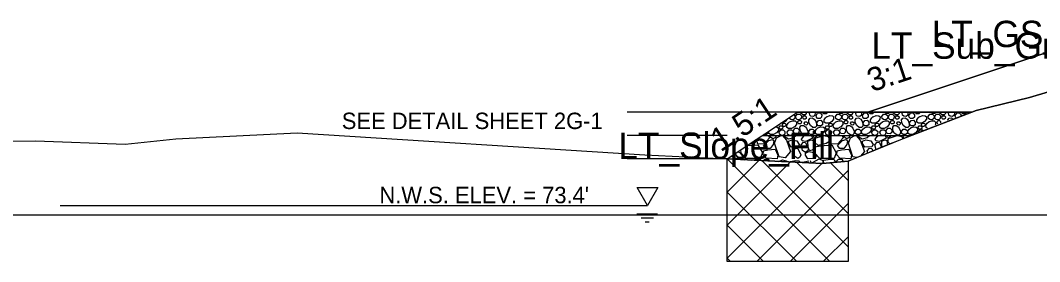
# Model space of a CAD drawing. Extents: x -14026 to 1303, y -10 to 9533.
# Drawn here: x 85.51 to 129.01, y 3498 to 3508.3 of the extents above; entities that cross this region are included whole.
import ezdxf

# ---------------------------------------------------------------- set-up
doc = ezdxf.new("R2010")
doc.units = 0
for name, color, linetype in [('Exist Cross Section Cell', 7, 'Continuous'), ('Exist XS Ground Line', 7, 'Continuous'), ('Old_Level_10', 7, 'Continuous'), ('Prop CMT Slope Grass', 7, 'Continuous'), ('Prop CMT Subgrade Earthwork', 7, 'Continuous'), ('Prop XS Earthwork Shape', 7, 'Continuous'), ('Prop XS Side Slope Text', 7, 'Continuous'), ('Scratch_Level_0', 7, 'Continuous'), ('Scratch_Level_1', 7, 'Continuous'), ('Scratch_Level_3', 7, 'Continuous'), ('Scratch_Level_5', 7, 'Continuous')]:
    doc.layers.add(name, color=color, linetype=linetype)

msp = doc.modelspace()

# ---------------------------------------------------------------- linework, layer by layer
at = {"layer": 'Exist Cross Section Cell'}
msp.add_line((0, 3500), (150, 3500), dxfattribs=at)
at = {"layer": 'Exist XS Ground Line'}
msp.add_lwpolyline([(80.656, 3503.087), (86.162, 3503.158), (89.984, 3503.012), (92.146, 3503.237), (97.323, 3503.503), (112.156, 3502.557), (119.746, 3502.185), (120.837, 3502.289), (122.384, 3502.944), (126.299, 3504.454), (128.568, 3505.004), (131.672, 3505.924)], dxfattribs=at)
at = {"layer": 'Old_Level_10'}
for p, q in [((119.183, 3504.338), (119.215, 3504.384)), ((121.162, 3504.338), (121.194, 3504.384)), ((122.702, 3504.384), (126.118, 3504.384)), ((123.14, 3504.338), (123.173, 3504.384)), ((125.119, 3504.338), (125.151, 3504.384)), ((117.177, 3503.384), (123.525, 3503.384)), ((123.208, 3503.255), (123.172, 3503.384)), ((123.828, 3503.519), (123.827, 3503.524)), ((116.897, 3503.197), (116.921, 3503.141)), ((117.463, 3502.306), (117.463, 3502.297)), ((119.209, 3502.318), (119.265, 3502.208)), ((120.284, 3502.262), (120.247, 3502.232)), ((120.611, 3502.306), (120.61, 3502.267))]:
    msp.add_line(p, q, dxfattribs=at)
msp.add_lwpolyline([(115.677, 3502.384), (118.677, 3504.384), (126.118, 3504.384), (123.525, 3503.384), (120.837, 3502.289), (119.746, 3502.185)], close=True, dxfattribs=at)
for points in [[(118.514, 3504.276), (118.568, 3504.22), (118.557, 3504.112), (118.491, 3504.057), (118.385, 3504.065), (118.335, 3504.113), (118.327, 3504.151)], [(118.624, 3504.349), (118.6, 3504.323), (118.586, 3504.323)], [(118.595, 3504.192), (118.662, 3504.288), (118.77, 3504.294), (118.844, 3504.216), (118.833, 3504.108), (118.767, 3504.053), (118.661, 3504.06), (118.611, 3504.109), (118.595, 3504.192)], [(119.056, 3504.384), (119.05, 3504.317), (118.998, 3504.262), (118.904, 3504.264), (118.798, 3504.347), (118.779, 3504.384)], [(119.411, 3504.384), (119.432, 3504.363), (119.421, 3504.254), (119.355, 3504.199), (119.249, 3504.207), (119.199, 3504.255), (119.183, 3504.338)], [(119.467, 3504.243), (119.534, 3504.339), (119.641, 3504.345), (119.716, 3504.268), (119.705, 3504.159), (119.639, 3504.104), (119.533, 3504.112), (119.483, 3504.16), (119.467, 3504.243)], [(119.949, 3504.384), (119.947, 3504.362), (119.895, 3504.307), (119.801, 3504.308), (119.704, 3504.384)], [(120.219, 3504.384), (120.2, 3504.369), (120.094, 3504.376), (120.086, 3504.384)], [(120.297, 3504.196), (120.364, 3504.292), (120.472, 3504.298), (120.546, 3504.22), (120.536, 3504.112), (120.469, 3504.057), (120.363, 3504.065), (120.313, 3504.113), (120.297, 3504.196)], [(120.631, 3504.384), (120.631, 3504.378), (120.578, 3504.323), (120.485, 3504.325), (120.408, 3504.384)], [(120.574, 3504.192), (120.641, 3504.288), (120.748, 3504.294), (120.823, 3504.216), (120.812, 3504.108), (120.746, 3504.053), (120.64, 3504.06), (120.59, 3504.109), (120.574, 3504.192)], [(121.035, 3504.384), (121.029, 3504.317), (120.977, 3504.262), (120.883, 3504.264), (120.777, 3504.347), (120.758, 3504.384)], [(121.39, 3504.384), (121.411, 3504.363), (121.4, 3504.254), (121.334, 3504.199), (121.228, 3504.207), (121.178, 3504.255), (121.162, 3504.338)], [(121.446, 3504.243), (121.513, 3504.339), (121.62, 3504.345), (121.695, 3504.268), (121.684, 3504.159), (121.618, 3504.104), (121.512, 3504.112), (121.462, 3504.16), (121.446, 3504.243)], [(121.928, 3504.384), (121.926, 3504.362), (121.874, 3504.307), (121.78, 3504.308), (121.683, 3504.384)], [(122.198, 3504.384), (122.179, 3504.369), (122.073, 3504.376), (122.065, 3504.384)], [(122.276, 3504.196), (122.343, 3504.292), (122.45, 3504.298), (122.525, 3504.22), (122.514, 3504.112), (122.448, 3504.057), (122.342, 3504.065), (122.292, 3504.113), (122.276, 3504.196)], [(122.61, 3504.384), (122.609, 3504.378), (122.557, 3504.323), (122.463, 3504.325), (122.387, 3504.384)], [(122.552, 3504.192), (122.62, 3504.288), (122.727, 3504.294), (122.802, 3504.216), (122.791, 3504.108), (122.725, 3504.053), (122.619, 3504.06), (122.569, 3504.109), (122.553, 3504.192)], [(123.014, 3504.384), (123.008, 3504.317), (122.956, 3504.262), (122.862, 3504.264), (122.755, 3504.347), (122.737, 3504.384)], [(123.369, 3504.384), (123.389, 3504.363), (123.379, 3504.254), (123.312, 3504.199), (123.206, 3504.207), (123.157, 3504.255), (123.14, 3504.338)], [(123.424, 3504.243), (123.492, 3504.339), (123.599, 3504.345), (123.674, 3504.268), (123.663, 3504.159), (123.596, 3504.104), (123.49, 3504.112), (123.441, 3504.16), (123.424, 3504.243)], [(123.907, 3504.384), (123.905, 3504.362), (123.853, 3504.307), (123.759, 3504.308), (123.662, 3504.384)], [(124.177, 3504.384), (124.158, 3504.369), (124.052, 3504.376), (124.043, 3504.384)], [(124.255, 3504.196), (124.322, 3504.292), (124.429, 3504.298), (124.504, 3504.22), (124.493, 3504.112), (124.427, 3504.057), (124.321, 3504.065), (124.271, 3504.113), (124.255, 3504.196)], [(124.589, 3504.384), (124.588, 3504.378), (124.536, 3504.323), (124.442, 3504.325), (124.366, 3504.384)], [(124.531, 3504.192), (124.598, 3504.288), (124.706, 3504.294), (124.78, 3504.216), (124.77, 3504.108), (124.703, 3504.053), (124.597, 3504.06), (124.547, 3504.109), (124.531, 3504.192)], [(124.992, 3504.384), (124.987, 3504.317), (124.934, 3504.262), (124.841, 3504.264), (124.734, 3504.347), (124.715, 3504.384)], [(125.347, 3504.384), (125.368, 3504.363), (125.357, 3504.254), (125.291, 3504.199), (125.185, 3504.207), (125.135, 3504.255), (125.119, 3504.338)], [(125.403, 3504.243), (125.47, 3504.339), (125.578, 3504.345), (125.652, 3504.268), (125.648, 3504.221)], [(125.433, 3504.147), (125.419, 3504.16), (125.403, 3504.243)], [(125.885, 3504.384), (125.883, 3504.362), (125.831, 3504.307), (125.737, 3504.308), (125.64, 3504.384)], [(126.084, 3504.372), (126.03, 3504.376), (126.022, 3504.384)], [(118.238, 3504.092), (118.238, 3504.081), (118.155, 3503.975), (118.026, 3503.91), (117.965, 3503.909)], [(118.034, 3503.85), (118.074, 3503.908), (118.139, 3503.911), (118.184, 3503.865), (118.177, 3503.8), (118.137, 3503.767), (118.074, 3503.771), (118.044, 3503.8), (118.034, 3503.85)], [(118.334, 3503.963), (118.459, 3504.012), (118.575, 3504.003), (118.63, 3503.95), (118.628, 3503.857), (118.545, 3503.75), (118.416, 3503.686), (118.295, 3503.684), (118.226, 3503.732), (118.22, 3503.829), (118.275, 3503.915), (118.339, 3503.966)], [(118.693, 3503.961), (118.733, 3504.018), (118.798, 3504.022), (118.842, 3503.975), (118.836, 3503.91), (118.796, 3503.877), (118.733, 3503.882), (118.703, 3503.911), (118.693, 3503.961)], [(119.059, 3503.7), (119.109, 3503.574), (119.099, 3503.459), (119.047, 3503.404), (118.953, 3503.406), (118.847, 3503.489), (118.782, 3503.618), (118.78, 3503.739), (118.829, 3503.807), (118.925, 3503.814), (119.012, 3503.758), (119.063, 3503.695)], [(118.901, 3504.162), (118.941, 3504.22), (119.006, 3504.223), (119.05, 3504.177), (119.044, 3504.112), (119.004, 3504.079), (118.941, 3504.084), (118.911, 3504.113), (118.901, 3504.162)], [(118.958, 3503.913), (118.998, 3503.971), (119.062, 3503.974), (119.107, 3503.928), (119.101, 3503.863), (119.061, 3503.83), (118.997, 3503.834), (118.967, 3503.864), (118.958, 3503.913)], [(119.44, 3504.017), (119.49, 3503.892), (119.48, 3503.776), (119.427, 3503.721), (119.334, 3503.723), (119.227, 3503.806), (119.163, 3503.935), (119.161, 3504.056), (119.209, 3504.125), (119.306, 3504.131), (119.392, 3504.076), (119.443, 3504.012)], [(119.497, 3503.929), (119.564, 3504.024), (119.671, 3504.031), (119.746, 3503.953), (119.735, 3503.845), (119.669, 3503.79), (119.563, 3503.797), (119.513, 3503.846), (119.497, 3503.929)], [(119.922, 3504.187), (120.048, 3504.237), (120.164, 3504.227), (120.218, 3504.175), (120.217, 3504.081), (120.133, 3503.975), (120.005, 3503.91), (119.883, 3503.908), (119.815, 3503.957), (119.808, 3504.053), (119.864, 3504.14), (119.927, 3504.191)], [(120.013, 3503.85), (120.053, 3503.908), (120.117, 3503.911), (120.162, 3503.865), (120.156, 3503.8), (120.116, 3503.767), (120.052, 3503.771), (120.022, 3503.8), (120.013, 3503.85)], [(120.312, 3503.963), (120.438, 3504.012), (120.554, 3504.003), (120.609, 3503.95), (120.607, 3503.857), (120.524, 3503.75), (120.395, 3503.686), (120.273, 3503.684), (120.205, 3503.732), (120.199, 3503.829), (120.254, 3503.915), (120.317, 3503.966)], [(120.672, 3503.961), (120.712, 3504.018), (120.776, 3504.022), (120.821, 3503.975), (120.815, 3503.91), (120.775, 3503.877), (120.711, 3503.882), (120.681, 3503.911), (120.672, 3503.961)], [(121.038, 3503.7), (121.088, 3503.574), (121.078, 3503.459), (121.026, 3503.404), (120.932, 3503.406), (120.825, 3503.489), (120.761, 3503.618), (120.759, 3503.739), (120.807, 3503.807), (120.904, 3503.814), (120.991, 3503.758), (121.041, 3503.695)], [(120.88, 3504.162), (120.92, 3504.22), (120.984, 3504.223), (121.029, 3504.177), (121.023, 3504.112), (120.983, 3504.079), (120.919, 3504.084), (120.889, 3504.113), (120.88, 3504.162)], [(120.936, 3503.913), (120.977, 3503.971), (121.041, 3503.974), (121.086, 3503.928), (121.079, 3503.863), (121.04, 3503.83), (120.976, 3503.834), (120.946, 3503.864), (120.936, 3503.913)], [(121.418, 3504.017), (121.468, 3503.892), (121.458, 3503.776), (121.406, 3503.721), (121.312, 3503.723), (121.206, 3503.806), (121.141, 3503.935), (121.139, 3504.056), (121.188, 3504.125), (121.285, 3504.131), (121.371, 3504.076), (121.422, 3504.012)], [(121.476, 3503.929), (121.543, 3504.024), (121.65, 3504.031), (121.725, 3503.953), (121.714, 3503.845), (121.648, 3503.79), (121.542, 3503.797), (121.492, 3503.846), (121.476, 3503.929)], [(121.901, 3504.187), (122.027, 3504.237), (122.142, 3504.227), (122.197, 3504.175), (122.195, 3504.081), (122.112, 3503.975), (121.983, 3503.91), (121.862, 3503.908), (121.794, 3503.957), (121.787, 3504.053), (121.843, 3504.14), (121.906, 3504.191)], [(121.991, 3503.85), (122.032, 3503.908), (122.096, 3503.911), (122.141, 3503.865), (122.134, 3503.8), (122.095, 3503.767), (122.031, 3503.771), (122.001, 3503.8), (121.991, 3503.85)], [(122.291, 3503.963), (122.417, 3504.012), (122.532, 3504.003), (122.587, 3503.95), (122.586, 3503.857), (122.502, 3503.75), (122.373, 3503.686), (122.252, 3503.684), (122.184, 3503.732), (122.177, 3503.829), (122.233, 3503.915), (122.296, 3503.966)], [(122.65, 3503.961), (122.691, 3504.018), (122.755, 3504.022), (122.8, 3503.975), (122.793, 3503.91), (122.754, 3503.877), (122.69, 3503.882), (122.66, 3503.911), (122.65, 3503.961)], [(123.017, 3503.7), (123.067, 3503.574), (123.057, 3503.459), (123.004, 3503.404), (122.911, 3503.406), (122.804, 3503.489), (122.74, 3503.618), (122.738, 3503.739), (122.786, 3503.807), (122.883, 3503.814), (122.969, 3503.758), (123.02, 3503.695)], [(122.858, 3504.162), (122.899, 3504.22), (122.963, 3504.223), (123.008, 3504.177), (123.001, 3504.112), (122.962, 3504.079), (122.898, 3504.084), (122.868, 3504.113), (122.858, 3504.162)], [(122.915, 3503.913), (122.955, 3503.971), (123.02, 3503.974), (123.065, 3503.928), (123.058, 3503.863), (123.018, 3503.83), (122.955, 3503.834), (122.925, 3503.864), (122.915, 3503.913)], [(123.397, 3504.017), (123.447, 3503.892), (123.437, 3503.776), (123.385, 3503.721), (123.291, 3503.723), (123.185, 3503.806), (123.12, 3503.935), (123.118, 3504.056), (123.167, 3504.125), (123.263, 3504.131), (123.35, 3504.076), (123.4, 3504.012)], [(123.454, 3503.929), (123.521, 3504.024), (123.629, 3504.031), (123.703, 3503.953), (123.693, 3503.845), (123.626, 3503.79), (123.52, 3503.797), (123.47, 3503.846), (123.454, 3503.929)], [(123.88, 3504.187), (124.005, 3504.237), (124.121, 3504.227), (124.176, 3504.175), (124.174, 3504.081), (124.091, 3503.975), (123.962, 3503.91), (123.841, 3503.908), (123.772, 3503.957), (123.766, 3504.053), (123.821, 3504.14), (123.885, 3504.191)], [(123.97, 3503.85), (124.01, 3503.908), (124.075, 3503.911), (124.12, 3503.865), (124.113, 3503.8), (124.073, 3503.767), (124.01, 3503.771), (123.98, 3503.8), (123.97, 3503.85)], [(124.218, 3503.693), (124.162, 3503.732), (124.156, 3503.829), (124.211, 3503.915), (124.275, 3503.966)], [(124.27, 3503.963), (124.396, 3504.012), (124.511, 3504.003), (124.566, 3503.95), (124.564, 3503.857), (124.553, 3503.842)], [(124.629, 3503.961), (124.669, 3504.018), (124.734, 3504.022), (124.779, 3503.975), (124.773, 3503.919)], [(124.668, 3503.882), (124.639, 3503.911), (124.629, 3503.961)], [(124.837, 3504.162), (124.877, 3504.22), (124.942, 3504.223), (124.987, 3504.177), (124.98, 3504.112), (124.94, 3504.079), (124.877, 3504.084), (124.847, 3504.113), (124.837, 3504.162)], [(125.097, 3504.031), (125.097, 3504.056), (125.145, 3504.125), (125.242, 3504.131), (125.293, 3504.099)], [(117.434, 3503.384), (117.473, 3503.278), (117.246, 3503.024), (116.984, 3503.007), (116.924, 3503.216)], [(117.423, 3503.548), (117.416, 3503.475), (117.35, 3503.42), (117.244, 3503.428), (117.243, 3503.428)], [(117.73, 3503.753), (117.806, 3503.746), (117.861, 3503.694), (117.86, 3503.6), (117.776, 3503.494), (117.647, 3503.429), (117.526, 3503.427), (117.458, 3503.476), (117.452, 3503.567)], [(117.624, 3503.24), (117.527, 3503.317), (117.502, 3503.384)], [(117.758, 3503.384), (117.734, 3503.301), (117.624, 3503.24)], [(118.035, 3503.378), (118.199, 3503.184), (118.381, 3502.704), (118.155, 3502.426), (117.89, 3502.471), (117.698, 3503.058), (117.782, 3503.286), (117.973, 3503.384)], [(117.891, 3503.524), (117.958, 3503.619), (118.065, 3503.625), (118.14, 3503.548), (118.129, 3503.44), (118.063, 3503.384), (117.957, 3503.392), (117.907, 3503.44), (117.891, 3503.524)], [(117.895, 3503.734), (117.936, 3503.791), (118, 3503.795), (118.045, 3503.748), (118.038, 3503.683), (117.999, 3503.65), (117.935, 3503.655), (117.905, 3503.684), (117.895, 3503.734)], [(118.617, 3503.384), (118.506, 3503.281), (118.289, 3503.228), (118.148, 3503.31), (118.142, 3503.384)], [(118.238, 3503.527), (118.305, 3503.623), (118.412, 3503.629), (118.487, 3503.552), (118.476, 3503.443), (118.41, 3503.388), (118.304, 3503.396), (118.254, 3503.444), (118.238, 3503.527)], [(118.498, 3503.598), (118.566, 3503.693), (118.673, 3503.699), (118.748, 3503.622), (118.737, 3503.514), (118.67, 3503.458), (118.564, 3503.466), (118.515, 3503.514), (118.498, 3503.598)], [(118.839, 3503.232), (118.94, 3503.354), (118.979, 3503.384)], [(119.273, 3503.384), (119.313, 3503.263), (119.026, 3503.121), (118.875, 3503.151), (118.839, 3503.232)], [(119.156, 3503.559), (119.223, 3503.655), (119.331, 3503.661), (119.405, 3503.583), (119.395, 3503.475), (119.328, 3503.42), (119.222, 3503.428), (119.172, 3503.476), (119.156, 3503.559)], [(119.38, 3503.28), (119.338, 3503.372), (119.332, 3503.384)], [(119.543, 3503.384), (119.49, 3503.34), (119.38, 3503.28)], [(120.069, 3503.141), (119.904, 3503.041), (119.551, 3502.958), (119.395, 3503.101), (119.389, 3503.251), (119.784, 3503.384)], [(119.544, 3503.706), (119.67, 3503.756), (119.785, 3503.746), (119.84, 3503.694), (119.838, 3503.6), (119.755, 3503.494), (119.626, 3503.429), (119.505, 3503.427), (119.436, 3503.476), (119.43, 3503.573), (119.485, 3503.659), (119.549, 3503.71)], [(119.799, 3503.384), (119.98, 3503.344), (120.069, 3503.141)], [(119.87, 3503.524), (119.937, 3503.619), (120.044, 3503.625), (120.119, 3503.548), (120.108, 3503.44), (120.042, 3503.384), (119.936, 3503.392), (119.886, 3503.44), (119.87, 3503.524)], [(119.874, 3503.734), (119.914, 3503.791), (119.979, 3503.795), (120.024, 3503.748), (120.017, 3503.683), (119.977, 3503.65), (119.914, 3503.655), (119.884, 3503.684), (119.874, 3503.734)], [(120.582, 3503.384), (120.621, 3503.278), (120.394, 3503.024), (120.132, 3503.007), (120.024, 3503.384)], [(120.216, 3503.527), (120.284, 3503.623), (120.391, 3503.629), (120.466, 3503.552), (120.455, 3503.443), (120.388, 3503.388), (120.282, 3503.396), (120.233, 3503.444), (120.216, 3503.527)], [(120.477, 3503.598), (120.544, 3503.693), (120.652, 3503.699), (120.726, 3503.622), (120.716, 3503.514), (120.649, 3503.458), (120.543, 3503.466), (120.493, 3503.514), (120.477, 3503.598)], [(120.771, 3503.24), (120.674, 3503.317), (120.649, 3503.384)], [(120.905, 3503.384), (120.881, 3503.301), (120.771, 3503.24)], [(121.211, 3502.441), (121.038, 3502.471), (120.845, 3503.058), (120.93, 3503.286), (121.121, 3503.384)], [(121.135, 3503.559), (121.202, 3503.655), (121.309, 3503.661), (121.384, 3503.583), (121.373, 3503.475), (121.307, 3503.42), (121.201, 3503.428), (121.151, 3503.476), (121.135, 3503.559)], [(121.183, 3503.378), (121.347, 3503.184), (121.529, 3502.704), (121.367, 3502.505)], [(121.765, 3503.384), (121.654, 3503.281), (121.437, 3503.228), (121.296, 3503.31), (121.29, 3503.384)], [(121.523, 3503.706), (121.648, 3503.756), (121.764, 3503.746), (121.819, 3503.694), (121.817, 3503.6), (121.734, 3503.494), (121.605, 3503.429), (121.484, 3503.427), (121.415, 3503.476), (121.409, 3503.573), (121.464, 3503.659), (121.528, 3503.71)], [(121.848, 3503.524), (121.915, 3503.619), (122.023, 3503.625), (122.097, 3503.548), (122.087, 3503.44), (122.02, 3503.384), (121.914, 3503.392), (121.864, 3503.44), (121.848, 3503.524)], [(121.853, 3503.734), (121.893, 3503.791), (121.957, 3503.795), (122.002, 3503.748), (121.996, 3503.683), (121.956, 3503.65), (121.892, 3503.655), (121.862, 3503.684), (121.853, 3503.734)], [(121.987, 3503.232), (122.087, 3503.354), (122.127, 3503.384)], [(122.42, 3503.384), (122.461, 3503.263), (122.174, 3503.121), (122.022, 3503.151), (121.987, 3503.232)], [(122.195, 3503.527), (122.262, 3503.623), (122.37, 3503.629), (122.444, 3503.552), (122.433, 3503.443), (122.367, 3503.388), (122.261, 3503.396), (122.211, 3503.444), (122.195, 3503.527)], [(122.456, 3503.598), (122.523, 3503.693), (122.63, 3503.699), (122.705, 3503.622), (122.694, 3503.514), (122.628, 3503.458), (122.522, 3503.466), (122.472, 3503.514), (122.456, 3503.598)], [(122.527, 3503.28), (122.486, 3503.372), (122.48, 3503.384)], [(122.69, 3503.384), (122.637, 3503.34), (122.527, 3503.28)], [(122.631, 3503.02), (122.543, 3503.101), (122.537, 3503.251), (122.932, 3503.384)], [(122.947, 3503.384), (123.127, 3503.344), (123.173, 3503.241)], [(123.114, 3503.559), (123.181, 3503.655), (123.288, 3503.661), (123.363, 3503.583), (123.352, 3503.475), (123.286, 3503.42), (123.18, 3503.428), (123.13, 3503.476), (123.114, 3503.559)], [(123.501, 3503.706), (123.627, 3503.756), (123.743, 3503.746), (123.797, 3503.694), (123.796, 3503.6), (123.712, 3503.494), (123.584, 3503.429), (123.462, 3503.427), (123.394, 3503.476), (123.387, 3503.573), (123.443, 3503.659), (123.506, 3503.71)], [(123.827, 3503.524), (123.894, 3503.619), (124.002, 3503.625), (124.021, 3503.605)], [(123.831, 3503.734), (123.872, 3503.791), (123.936, 3503.795), (123.981, 3503.748), (123.974, 3503.683), (123.935, 3503.65), (123.871, 3503.655), (123.841, 3503.684), (123.831, 3503.734)], [(116.526, 3502.95), (116.989, 3502.992), (117.184, 3502.65), (117.088, 3502.402), (116.487, 3502.403), (116.265, 3502.632), (116.256, 3502.77)], [(116.921, 3503.141), (116.757, 3503.041), (116.61, 3503.006)], [(117.661, 3503.135), (117.638, 3503.004), (117.504, 3502.835), (117.327, 3502.827), (117.229, 3502.956), (117.451, 3503.164), (117.602, 3503.208), (117.661, 3503.135)], [(118.296, 3503.142), (118.444, 3503.205), (118.652, 3503.163), (118.753, 3502.998), (118.7, 3502.902), (118.401, 3502.884), (118.3, 3503.049), (118.296, 3503.142)], [(119.016, 3502.657), (118.894, 3502.74), (118.828, 3502.981), (118.929, 3503.104), (119.023, 3503.089), (119.141, 3502.819), (119.107, 3502.723), (119.016, 3502.657)], [(119.189, 3502.727), (119.129, 3502.881), (119.123, 3503.136), (119.256, 3503.195), (119.341, 3503.171), (119.379, 3502.849), (119.295, 3502.756), (119.189, 3502.727)], [(119.396, 3502.894), (119.65, 3502.948), (120.136, 3502.992), (120.332, 3502.65), (120.235, 3502.402), (119.635, 3502.403), (119.413, 3502.632), (119.396, 3502.894)], [(120.809, 3503.135), (120.785, 3503.004), (120.652, 3502.835), (120.475, 3502.827), (120.377, 3502.956), (120.598, 3503.164), (120.75, 3503.208), (120.809, 3503.135)], [(121.444, 3503.142), (121.592, 3503.205), (121.8, 3503.163), (121.9, 3502.998), (121.848, 3502.902), (121.548, 3502.884), (121.448, 3503.049), (121.444, 3503.142)], [(122.031, 3502.776), (121.975, 3502.981), (122.077, 3503.104), (122.171, 3503.089), (122.266, 3502.871)], [(122.278, 3502.876), (122.276, 3502.881), (122.27, 3503.136), (122.404, 3503.195), (122.488, 3503.171), (122.512, 3502.971)], [(116.124, 3502.682), (116.218, 3502.663), (116.325, 3502.499), (116.272, 3502.403), (115.973, 3502.384), (115.881, 3502.52)], [(117.223, 3502.733), (117.403, 3502.778), (117.721, 3502.797), (117.838, 3502.539), (117.806, 3502.394), (117.336, 3502.418), (117.211, 3502.563), (117.223, 3502.733)], [(118.686, 3502.399), (118.564, 3502.482), (118.498, 3502.723), (118.599, 3502.846), (118.694, 3502.831), (118.811, 3502.56), (118.777, 3502.465), (118.686, 3502.399)], [(119.01, 3502.636), (119.158, 3502.705), (119.366, 3502.663), (119.472, 3502.499), (119.42, 3502.403), (119.121, 3502.384), (119.014, 3502.543), (119.01, 3502.636)], [(120.371, 3502.733), (120.55, 3502.778), (120.868, 3502.797), (120.985, 3502.539), (120.954, 3502.394), (120.483, 3502.418), (120.359, 3502.563), (120.371, 3502.733)], [(121.671, 3502.629), (121.645, 3502.723), (121.747, 3502.846), (121.841, 3502.831), (121.89, 3502.718)], [(116.388, 3502.349), (116.454, 3502.384), (116.549, 3502.341)], [(116.696, 3502.334), (116.937, 3502.379), (117.088, 3502.354), (117.109, 3502.314)], [(117.207, 3502.309), (117.274, 3502.371), (117.423, 3502.373), (117.463, 3502.306)], [(117.882, 3502.276), (118.029, 3502.349), (118.2, 3502.299), (118.203, 3502.26)], [(118.291, 3502.256), (118.291, 3502.266), (118.589, 3502.322), (118.74, 3502.296), (118.773, 3502.232)], [(118.888, 3502.227), (118.892, 3502.249), (119.153, 3502.297)], [(119.309, 3502.206), (119.308, 3502.228), (119.602, 3502.384), (119.755, 3502.315), (119.76, 3502.186)], [(119.798, 3502.189), (119.787, 3502.324), (120.085, 3502.379), (120.236, 3502.354), (120.284, 3502.262)], [(120.276, 3502.235), (120.422, 3502.371), (120.571, 3502.373), (120.611, 3502.306)]]:
    msp.add_lwpolyline(points, dxfattribs=at)
at = {"layer": 'Prop CMT Slope Grass'}
msp.add_line((121.677, 3504.384), (126.118, 3504.384), dxfattribs=at)
msp.add_lwpolyline([(130, 3507.156), (121.677, 3504.384)], dxfattribs=at)
at = {"layer": 'Prop CMT Subgrade Earthwork'}
msp.add_line((121.677, 3504.384), (126.118, 3504.384), dxfattribs=at)
for points in [[(130, 3507.156), (128.506, 3506.658)], [(128.506, 3506.658), (121.677, 3504.384)]]:
    msp.add_lwpolyline(points, dxfattribs=at)
at = {"layer": 'Prop XS Earthwork Shape'}
msp.add_lwpolyline([(137.793, 3506.891), (135.19, 3506.826), (134.5, 3507.516), (130, 3507.156), (128.506, 3506.658), (121.677, 3504.384), (126.118, 3504.384), (126.299, 3504.454), (128.568, 3505.004), (131.672, 3505.924), (134.599, 3506.537), (135.621, 3506.748)], close=True, dxfattribs=at)
msp.add_lwpolyline([(131.672, 3505.924), (128.568, 3505.004), (126.299, 3504.454), (126.118, 3504.384), (121.677, 3504.384), (130, 3507.156)], dxfattribs=at)
at = {"layer": 'Prop XS Side Slope Text'}
for p, q in [((111.824, 3500.046), (112.699, 3500.046)), ((111.999, 3499.871), (112.524, 3499.871)), ((112.174, 3499.696), (112.349, 3499.696))]:
    msp.add_line(p, q, dxfattribs=at)
msp.add_lwpolyline([(111.837, 3501.159), (112.712, 3501.159), (112.274, 3500.4)], close=True, dxfattribs=at)
at = {"layer": 'Scratch_Level_1'}
msp.add_line((87.209, 3500.4), (112.274, 3500.4), dxfattribs=at)
at = {"layer": 'Scratch_Level_3'}
for p, q in [((121.677, 3504.384), (111.412, 3504.384)), ((115.671, 3503.384), (111.412, 3503.384)), ((115.671, 3502.384), (111.412, 3502.384))]:
    msp.add_line(p, q, dxfattribs=at)
at = {"layer": 'Scratch_Level_5'}
for p, q in [((115.671, 3502.384), (120.056, 3498)), ((115.671, 3500.97), (117.02, 3502.318)), ((115.671, 3499.556), (118.368, 3502.252)), ((115.671, 3498.142), (119.716, 3502.186)), ((117.159, 3502.311), (120.837, 3498.633)), ((118.646, 3502.238), (120.837, 3500.047)), ((120.082, 3502.217), (120.837, 3501.462)), ((116.944, 3498), (120.837, 3501.893)), ((115.671, 3500.97), (118.642, 3498)), ((118.358, 3498), (120.837, 3500.479)), ((115.671, 3499.556), (117.227, 3498)), ((119.772, 3498), (120.837, 3499.065)), ((115.671, 3498.142), (115.813, 3498))]:
    msp.add_line(p, q, dxfattribs=at)
msp.add_lwpolyline([(120.837, 3502.289), (120.837, 3498), (115.671, 3498), (115.671, 3502.384), (119.746, 3502.185)], close=True, dxfattribs=at)

# ---------------------------------------------------------------- texts
at = {"layer": 'Old_Level_10'}
msp.add_text('SEE DETAIL SHEET 2G-1', height=0.7, dxfattribs=at).set_placement((99.228, 3503.659))
at = {"layer": 'Prop XS Side Slope Text'}
for s, rotation, p in [('3:1', 18.4178, (121.847, 3505.231)), ('1.5:1', 33.6901, (115.396, 3502.656))]:
    msp.add_text(s, height=1, rotation=rotation, dxfattribs=at).set_placement(p)
msp.add_text("N.W.S. ELEV. = 73.4'", height=0.7, dxfattribs=at).set_placement((100.833, 3500.493))
at = {"layer": 'Scratch_Level_0'}
for s, p in [('LT_GS_OS_CTL', (124.4, 3507.156)), ('LT_Sub_Graded_Tie', (121.827, 3506.658)), ('LT_Slope_Fill', (111.031, 3502.384))]:
    msp.add_text(s, height=1.125, dxfattribs=at).set_placement(p)

doc.saveas('drawing.dxf')
